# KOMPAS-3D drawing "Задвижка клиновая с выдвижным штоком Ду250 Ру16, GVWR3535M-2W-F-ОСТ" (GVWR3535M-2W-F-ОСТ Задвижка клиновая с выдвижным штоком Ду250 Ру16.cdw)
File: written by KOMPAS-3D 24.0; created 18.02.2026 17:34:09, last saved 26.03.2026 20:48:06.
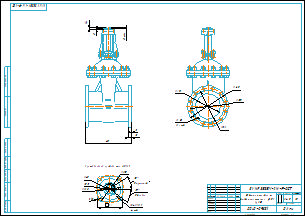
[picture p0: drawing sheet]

Document properties: Автор: R2D2; Форматы листов документа: A2; Полное имя файла: GVWR3535M-2W-F-ОСТ Задвижка клиновая с выдвижным штоком Ду250 Ру16.m3d; Масса: 142.5; Наименование: Задвижка клиновая с выдвижным штоком Ду250 Ру16; Количество листов документа: 1; Примечание: D040-09831

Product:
- Part/product: Задвижка клиновая с выдвижным штоком Ду250 Ру16  | designation GVWR3535M-2W-F-ОСТ
    Масса: 142.5
    Раздел спецификации: Прочие изделия
    Примечание: D040-09831

Views: Проекционный вид 2
Referenced files in E:\Работа\Зайцев\Для компаса\: чертеж DN.ru А3.cdt
Referenced files in E:\Работа\Зайцев\GVWR3535M-2W-F-ОСТ Задвижка клиновая 30нж941нж DN.ru Ду50-200 Ру16\исходные данные\DN250\dn250\: GVWR3535M-2W-F-ОСТ Задвижка клиновая с выдвижным штоком Ду250 Ру16.m3d
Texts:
  Присоединение привода тип АК (Б)
  чертеж DN.ru А3.cdt
  Задвижка клиновая с
  выдвижным штоком Ду250
  Ру16
  GVWR3535M-2W-F-ОСТ
  Задвижка клиновая с выдвижным штоком Ду250 Ру16
  GVWR3535M-2W-F-ОСТ Задвижка клиновая с выдвижным штоком Ду250 Ру16
Dimensions and other numbers on the sheet: 108; 45; 59; 135; 13; 14 (М12); 4 отв.; 122; 5 впадин; 5 кулачков; 1:5; 0; 1; 2; 142,5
